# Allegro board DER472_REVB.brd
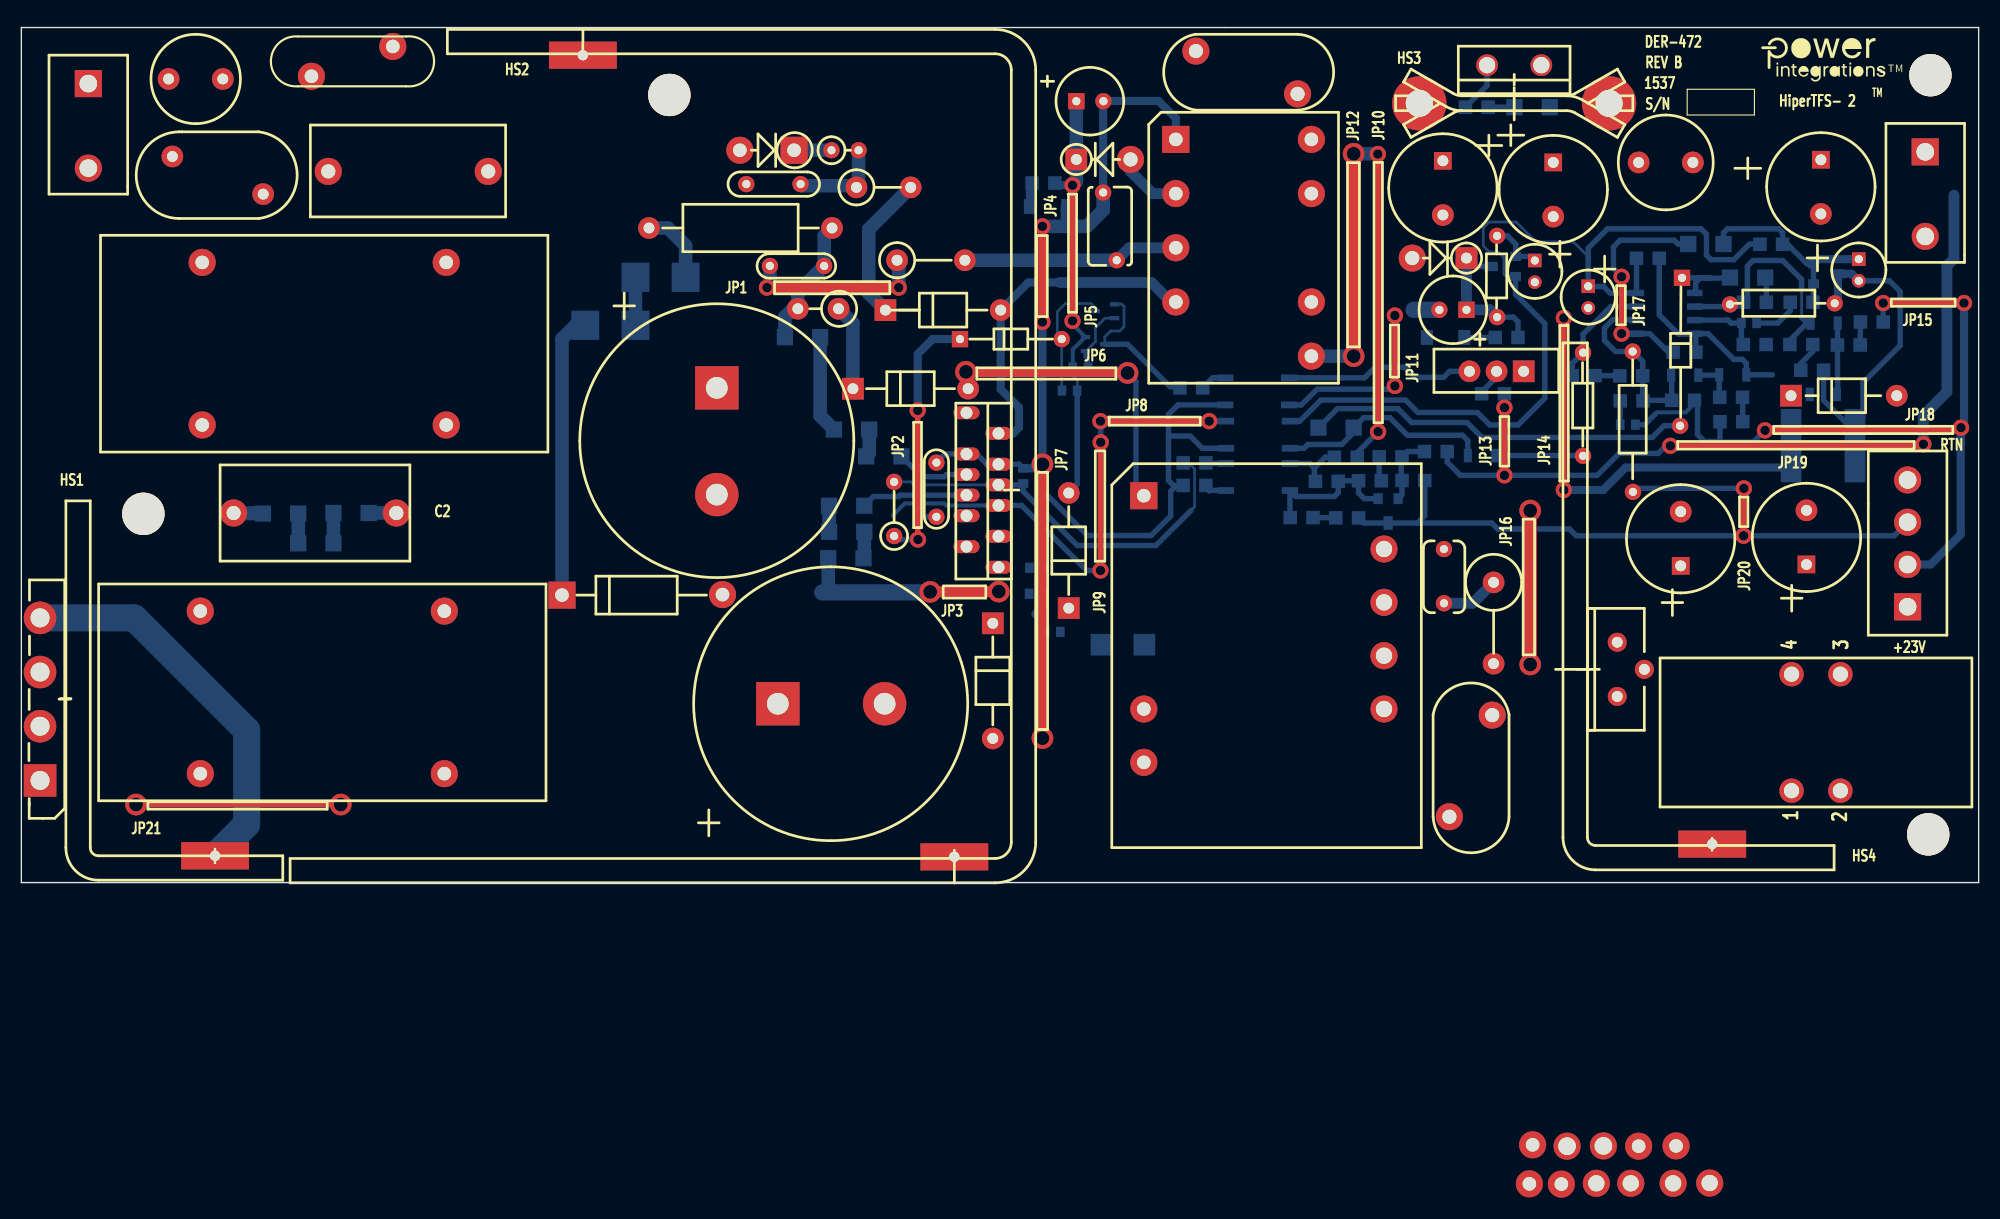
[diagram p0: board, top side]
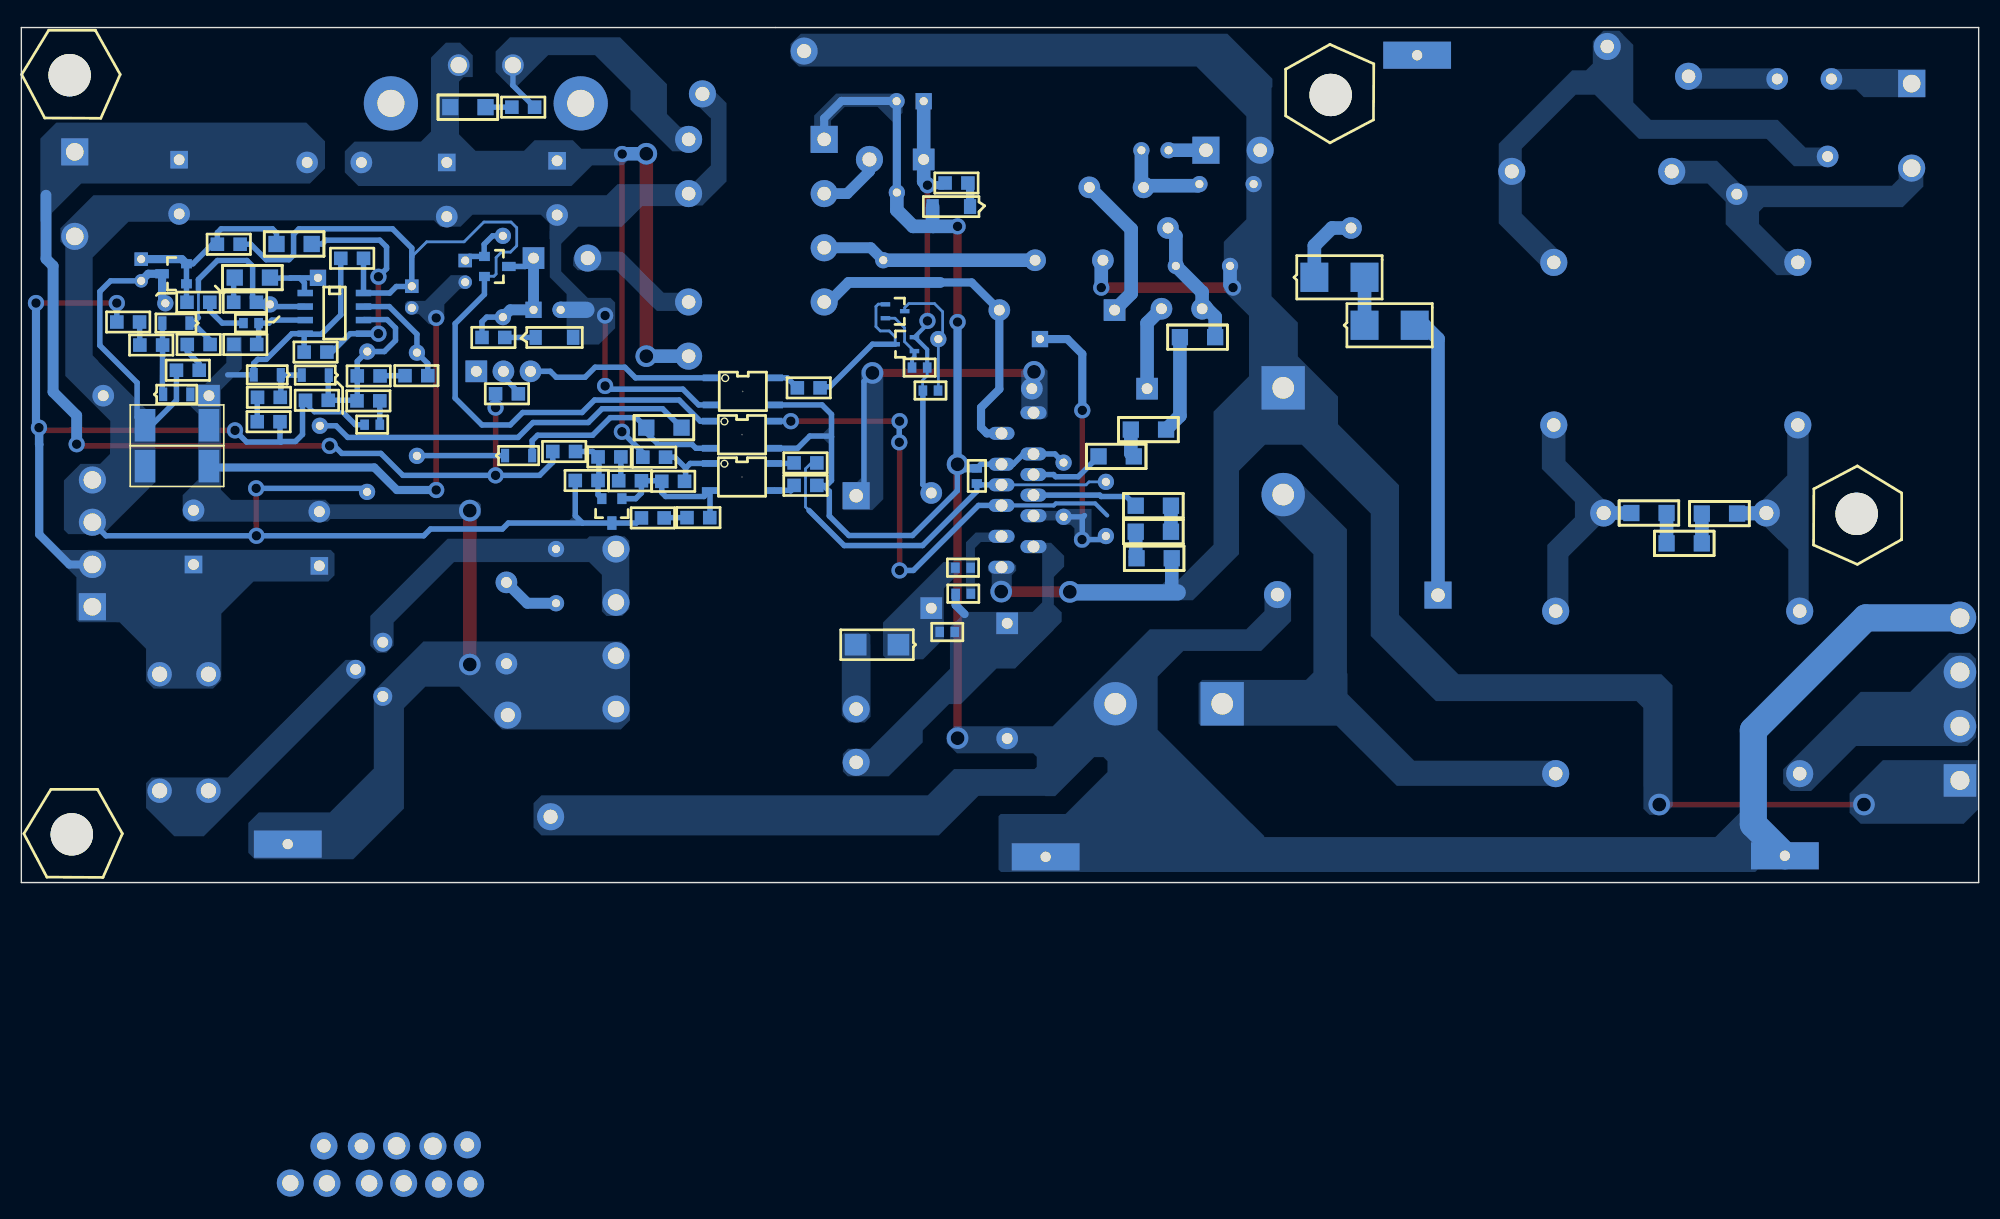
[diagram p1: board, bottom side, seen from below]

Outline 183.36 x 80.16 mm; copper layers: TOP, BOTTOM. Coordinates in mm from the lower left corner of the outline.
Outline path: 0,80.16 183.36,80.16 183.36,0 0,0 0,80.16

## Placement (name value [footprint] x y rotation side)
BR1  GBU8J  [PIDAXBRIDGEGBU8]  1.75 9.58 90 top
C1  220 nF  [PINPXCAPRAD720X340590040]  28.75 66.67 0 top
C2  470 nF  [PI_NP_CAP700X355LS600D040]  35.13 34.65 180 top
C3  680 uF  [PIPOLCAPCLYD948LS394080]  65.18 46.38 270 top
C4  680 uF  [PIPOLCAPCLYD948LS394080]  70.87 16.79 0 top
C5  2.2 nF  [PINPCAPRAD200X100200030]  75.21 57.81 180 top
C6  100 nF  [PISMC0603]  94.41 27.08 0 bottom
C7  100 nF  [PISMC0603]  97.33 23.5 180 bottom
C8  10 uF  [PINPCAPRAD200X100200030]  85.73 34.29 90 top
C9  220pF  [PISMC0603]  93.85 37.41 90 bottom
C10  4.7 nF  [PINPCAPRAD640X260375040]  133.76 6.17 90 top
C11  2.2 nF  [PINPCAPRAD350X100200030]  67.92 65.48 0 top
C12  47 pF  [PINPCAPRAD180X160200030]  133.27 31.27 270 top
C13  150 uF  [PIPOLCAPCYLD400LS200040]  167.23 29.82 90 top
C14  150 uF  [PIPOLCAPCYLD400LS200040]  155.45 29.69 90 top
C15  47 pF  [PISMC0805]  170.13 50.39 0 bottom
C16  680 pF  [PISMC0603]  149.78 42.93 0 bottom
C17  10 nf  [PISMC0805]  145.29 47.52 0 bottom
C18  15 nF  [PISMC0805]  159.11 45.49 0 bottom
C19  10 nf  [PISMC0805]  154.74 49.73 0 bottom
C20  10 uF  [PIPOLCAPCLYD200LS80030]  141.78 58.32 270 top
C21  100 nF  [PISMC0805]  151.31 58.52 0 bottom
C22  10 uF  [PIPOLCAPCLYD200LS80030]  146.79 55.91 270 top
C23  47 nF  [PISMC0805]  163.47 54.41 180 bottom
C24  10 uF  [PIPOLCAPCLYD200LS80030]  172.14 58.45 270 top
C25  15 nF  [PISMC0805]  166.7 48.03 0 bottom
C26  4.7 nF  [PINPCAPRAD640X260375040]  119.56 73.91 180 top
C27  1.0 nF  [PINPCAPRAD290X160250030]  101.35 64.69 270 top
C28  100 uF  [PIPOLCAPCYLD250LS100030]  98.83 73.25 0 top
C29  1 nF  [PISMC0805]  135.28 72.69 0 bottom
C30  100 uF  [PIPOLCAPCYLD250LS100030]  135.38 53.7 180 top
C31  1200 uF  [PIPOLCAPCYLD400LS200040]  133.17 67.67 270 top
C32  1200 uF  [PIPOLCAPCYLD400LS200040]  143.51 67.51 270 top
C33  2.2 uF  [PISMC0805]  121.01 34.21 180 bottom
C34  330 nF  [PISMC0805]  127.2 39.9 0 bottom
C35  330 uF  [PIPOLCAPCYLD400LS200040]  168.58 67.77 270 top
D1  1N4148  [PIDAX375X070030DO35#2]  87.93 50.95 0 top
D2  1N4007  [PIDAX475X125040DO41]  77.9 46.3 0 top
D3  US1D  [PISMDSMA]  101.19 22.3 0 bottom
D4  UF4005  [PIDAX475X125040DO41]  91.01 24.31 270 top
D5  UF4005  [PIDAX475X125040DO41]  98.12 25.73 90 top
D6  1N4007  [PIDV200X110X040DO41#2]  80.95 53.67 0 top
D7  STTH2003CT  [PIDVTO2203VF1]  149.5 19.99 90 top
D8  1N4148  [PIDAX375X070030DO35]  155.42 53.34 270 top
D9  BAV19WS  [PISMSOD323]  138.05 40.03 180 bottom
D10  BAV19WS  [PISMSOD323]  154.56 47.57 0 bottom
D11  BAV19WS  [PISMSOD323]  159.05 47.6 0 bottom
D12  BAV19WS  [PISMSOD323]  170.08 45.77 180 bottom
D13  BAV19WS  [PISMSOD323]  167.61 52.45 0 bottom
D14  1N4002-E3/54  [PIDV200X110X040DO41#3]  165.79 45.64 0 top
D15  UF4003  [PIDV200X110X040DO41]  98.83 67.79 0 top
D16  MBR1045  [PIDVT0220ACREVA]  137.31 76.63 0 top
D17  UF4003  [PIDV200X110X040DO41]  135.38 58.55 180 top
F1  5 A  [PI_TR5_SUBMIN_FUSE]  13.79 75.34 0 top
HS1  HEATSINK, HS POST, PI CUST  [PI_HS_DER472_BRIDGE]  4.17 17.25 270 top
HS2  HEATSINK, HS POST, PI CUST  [PI_HS_DER472_ESIP]  92.74 36.8 90 top
HS3  HEATSINK  [PI_HS_TO220_VERT]  139.85 73.05 0 top
HS4  HEATSINK, HS POST, PI CUST  [PI_HS_DER472_DIODE]  146.71 19.99 270 top
J1  CON3  [PI_HDR_3PIN#2]  6.27 74.9 180 top
J2  CON4  [PI_HDR_4PIN]  176.71 25.86 0 top
J5  CON3  [PI_HDR_3PIN]  178.36 68.5 180 top
L1  7.3 mH  [PIIND4P1650X800LS900X600050]  16.94 42.9 90 top
L2  7.3 mH  [PIIND4P1650X800LS900X600050]  16.76 10.21 90 top
L3  318 uH  [PI_IND_4P_TOROIDAL]  168.12 14.07 90 top
L4  2.2 Uh  [PI_CHOKE_COILCRAFT_RFB0807]  151.51 67.51 0 top
NOREF  -  []  183.36 0 90 top
NOREF#2  -  []  -204.37 -162.2 0 top
NOREF#3  -  []  163.02 79.65 0 top
NOREF#4  -  []  0.03 0 0 top
NOREF#5  -  []  -126.55 36.81 0 top
POST1  Post Hex, 6-32, snap, 0.375L, NYL  [PIMTGHOLED156]  11.43 34.57 270 bottom
POST2  Post Hex, 6-32, snap, 0.375L, NYL  [PIMTGHOLED156]  178.84 75.69 180 bottom
POST3  Post Hex, 6-32, snap, 0.375L, NYL  [PIMTGHOLED156]  178.64 4.52 180 bottom
POST4  Post Hex, 6-32, snap, 0.375L, NYL  [PIMTGHOLED156]  60.71 73.84 90 bottom
Q1  MMST4403-7-F  [PISMSOT323132]  99.7 49.81 90 bottom
Q2  MMST4403-7-F  [PISMSOT323132]  102.41 54.23 270 bottom
Q3  MMBT4401LT1G  [PISMSOT23123_1]  139.98 56.82 270 bottom
R1  680 k  [PISMR1206]  22.63 34.59 0 bottom
R2  680 k  [PISMR1206]  25.93 31.8 0 bottom
R3  680 k  [PISMR1206]  29.24 34.65 0 bottom
R4  82  [PISMR0603]  99.92 48.29 180 bottom
R5  7.5 k  [PISMR0603]  97.49 46.13 0 bottom
R6  10 k  [PISMR0805]  110.67 46.38 180 bottom
R7  100  [PI12WVRESD180LS150D040#2]  58.8 61.37 0 top
R8  931 k  [PISMR1206]  71.53 51.13 0 bottom
R9  931 k  [PISMR1206]  76.12 42.47 0 bottom
R10  976 k  [PISMR1206]  82.45 39.95 180 bottom
R11  931 k  [PISMR1206]  78.89 30.4 180 bottom
R12  931 k  [PISMR1206]  78.97 32.89 180 bottom
R13  976 k  [PISMR1206]  78.97 35.33 180 bottom
R14  2.2  [PI12WVRESD180LS150D040]  72.75 53.8 0 top
R15  1 k  [PISMR0603]  94.44 29.51 0 bottom
R16  107 k  [PI14WVRESD100LS200D030]  81.76 32.49 90 top
R17  0.0  [PISMR0805]  108.84 39.34 0 bottom
R18  0.0  [PISMR0805]  110.97 37.24 180 bottom
R19  22 k  [PI14WVRESD100LS100D030]  75.9 68.66 0 top
R20  6.8  [PI12WVRESD180LS150D040#4]  78.23 65.18 0 top
R21  15  [PI2WVRESD200LS300D040]  137.92 28.14 270 top
R22  10 k  [PISMR0805]  174.42 52.55 180 bottom
R23  3.3 k  [PISMR1206]  121.51 42.65 0 bottom
R24  3.3 k  [PI18WRESD080LS300D030]  146.3 47.62 270 top
R25  33 k  [PISMR0805]  149.76 47.5 0 bottom
R26  15 k  [PISMR0805]  149.78 45.16 0 bottom
R27  232 k  [PISMR0805]  156.74 45.21 180 bottom
R28  10 k  [PISMR0805]  159.13 43.21 0 bottom
R29  10.0 k  [PI14WRESD100LS400D030#2]  150.95 49.78 270 top
R30  10 k  [PISMR1206]  156.16 59.87 0 bottom
R31  10 k  [PI18WVRESD80LS100D030]  138.25 60.63 270 top
R32  4.7 k  [PISMR0805]  162.86 59.84 0 bottom
R33  3.3 k  [PISMR1206]  160.07 56.72 0 bottom
R34  100 k  [PISMR0805]  167.84 54.41 180 bottom
R35  8.66 k  [PISMR0603]  162.56 52.45 180 bottom
R36  15 k  [PI14WRESD100LS400D030]  159.72 54.31 0 top
R37  2.2 k  [PISMR0805]  165.68 50.44 0 bottom
R38  10 k  [PISMR0805]  161.32 50.44 0 bottom
R39  0.1  [PISMR2512]  165.79 39.04 0 bottom
R40  0.1  [PISMR2512]  165.79 42.88 0 bottom
R41  2.2  [PI12WVRESD180LS150D040#3]  82.04 58.34 0 top
R42  1 k  [PISMR0805]  94.69 65.58 0 bottom
R43  4.7  [PISMR1206]  143.18 72.69 180 bottom
R44  1 k  [PISMR0805]  138.07 51.1 0 bottom
R45  100  [PISMR0805]  123.01 39.88 0 bottom
R46  1 k  [PISMR0805]  121.23 37.62 0 bottom
R47  680  [PISMR0805]  123.14 34.19 0 bottom
R48  1 k  [PISMR0805]  125.27 37.67 0 bottom
R49  4.99 k  [PISMR0805]  133.58 40.41 180 bottom
R50  4.7 k  [PISMR0805]  138.94 45.82 180 bottom
R51  4.99 k  [PISMR0805]  129.34 37.69 0 bottom
RT1  2.5  [PI_RAD185X610LS300D031]  27.18 75.59 0 top
RV1  175 VAC  [PI_DISC_575X320_LS335X140D040]  14.15 68.07 0 top
SW1  SPDT SLIDE  [PI_SWITCH_SPDT_SLIDE_PCBM_1]  140.74 47.93 90 top
T1  EER35  [PI_BOBBIN_EER35_14P]  105.16 36.27 0 top
T2  EF25  [PI_BOBBIN_EF25_10P]  108.15 69.67 0 top
U1  TFS-7707H  [PI_IC_ESIP16-12_OVAL_SLOT_RECPT]  91.54 44.04 270 top
U2  LM431BIM3/NOPB  [PISMSOT23123]  167.89 58.01 90 bottom
U3  LM358ADR2G  [PISMSO8]  156.77 55.27 270 bottom
U4  PC357A  [PI_4_SMD]  115.85 41.99 270 bottom
U5  PC357A  [PI_4_SMD]  115.77 46.05 270 bottom
U6  PC357A  [PI_4_SMD]  115.85 38.02 270 bottom
U7  LM431AIM3  [PISMSOT23123]  128.98 35.99 0 bottom
VR1  SMBJ150A  [PISMDO214AA12]  62.23 56.74 180 bottom
VR2  SMBJ150A  [PISMDO214AA12]  57.53 52.25 180 bottom
VR3  P6KE170A  [PIDAX550X140050DO15DO204AC]  50.65 26.95 0 top
VR4  P6KE150A  [PIDV200X140X050DO15DO204AC]  72.39 68.66 180 top
VR5  MMSZ5248B-7-F  [PI_SM_SOD-123_12]  94.49 63.37 0 bottom
VR6  MMSZ5248B-7-F  [PI_SM_SOD-123_12]  135.18 51.1 180 bottom

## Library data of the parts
BR1 = DISCRETE BRIDGE_+~~-
C1 C5-C12 C15-C19 C21 C23 C25-C27 C29 C33 C34 = CAP NP
C2 = CAP NP: tolerance: 20
C3 C4 C13 C14 C31 C32 = CAP POL
C20 C22 C24 = CAP POL: alternate symbols: (pipolcapclyd200ls80030h)
C28 C30 = CAP POL: alternate symbols: (pipolcapclyd250ls100d30h590); tolerance: 20
C35 = CAP POL: alternate symbols: (pipolcapclyd400x530ls200030h)
D1 D8 = DIODE: alternate symbols: (pidax375x070030do35,pidv100x080x030do35)
D2 D6 D14 D15 D17 = DIODE: alternate symbols: (pidax475x125040do41,pidv200x110x040do41wbead,pidax390x125040do41)
D3 D9-D13 = DIODE
D4 D5 = DIODE: alternate symbols: (pidax475x125040do41,pidax390x125040do41)
D7 = D_DUAL_CK_ACA_3: alternate symbols: (pidvto2203vf1)
D16 = DIODE SCHOTTKY
F1 = FUSE
HS1 HS4 = HS-PI_CUSTOM1
HS2 HS3 = HS-PI_CUSTOM2
J1 J5 = CON3
J2 = CON4
L1 L2 = INDUCTOR_4P_revD
L3 = INDUCTOR_4P_SD
L4 = INDUCTOR
POST1-POST4 = POST_CRKT_BRD_6-32_HEX
Q1 Q2 = PNP_BEC
Q3 = NPN_BEC
R1-R6 R8-R11 R17 R18 R22 R23 R25-R28 R30 R32-R35 R37-R40 R42-R51 = R
R7 R14 R20 R41 = R: alternate symbols: (pi12wvresd180ls200d040,pi12wvresd180ls250d040,pi12wresd180ls675d040)
R12 R13 = R: tolerance: 1%
R15 = R: tolerance: 5%
R16 R19 R29 = R: alternate symbols: (pi14wvresd100ls200d030,pi14wresd100ls400d030,pi14wresd100ls500d030)
R21 = R: alternate symbols: (pi2wresd200ls900d040,pi2wvresd200ls300d040,pi2wvresd200ls400d040)
R24 R31 = R: alternate symbols: (pi18wresd080ls300d030)
R36 = R: alternate symbols: (pi14wvresd100ls200d030,pi14wresd100ls400d030,pi14wresd100ls500d030); tolerance: 1%
RT1 = THERMISTOR: alternate symbols: (pi_np_ycap_rad600ls400d040_h)
RV1 = VARISTOR
SW1 = SW SLIDE-SPDT
T1 = BEER35_14P/GENERIC
T2 = BF25_10P/GENERIC
U1 = HiperTFS_II_I_2_ROW: alternate symbols: (pi_ic_esip16-12_oval_slot_recpt)
U2 U7 = TL431/SOT-23_CAR
U3 = LM358
U4-U6 = OPTO_A_B
VR1 VR2 VR5 VR6 = DIODE_ZENER
VR3 VR4 = DIODE_ZENER: alternate symbols: (pidax550x140050do15do204ac)

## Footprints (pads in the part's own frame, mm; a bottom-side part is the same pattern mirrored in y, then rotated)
PI2WVRESD200LS300D040
  round 2.032 hole 1.016: 1(0,0) 2(7.62,0)
PI12WVRESD180LS150D040
  round 2.032 hole 1.016: 1(0,0) 2(3.81,0)
PI12WVRESD180LS150D040#2
  round 2.032 hole 1.016: 1(0,0) 2(17.145,0)
PI12WVRESD180LS150D040#3
  round 2.032 hole 1.016: 1(0,0) 2(6.35,0)
PI12WVRESD180LS150D040#4
  round 2.032 hole 1.016: 1(0,0) 2(5.08,0)
PI14WRESD100LS400D030
  round 1.524 hole 0.762: 1(0.356,-0.102) 2(10.16,0)
PI14WRESD100LS400D030#2
  round 1.524 hole 0.762: 1(0,0) 2(13.157,0.025)
PI14WVRESD100LS100D030
  round 1.524 hole 0.762: 1(0,0) 2(2.54,0)
PI14WVRESD100LS200D030
  round 1.524 hole 0.762: 1(0,0) 2(5.08,0)
PI18WRESD080LS300D030
  round 1.524 hole 0.762: 1(-2.057,0) 2(7.62,0)
PI18WVRESD80LS100D030
  round 1.524 hole 0.762: 1(0,0) 2(7.62,0)
PI_4_SMD
  rect 0.635x1.524 smd: 1(-1.27,-2.997) 2(1.27,-2.997) 3(1.27,2.997) 4(-1.27,2.997)
PI_BOBBIN_EER35_14P
  rect 2.54x2.54 hole 1.27: 1(0,0)
  round 2.54 hole 1.27: 2(36.119,-64.516) 3(39.116,-64.541) 4(36.424,-60.858) 5(0,-20) 6(0,-25.001)
  round 2.54 hole 1.524: 7(45.618,-64.465) 8(49.581,-64.465) 9(53.01,-64.44) 10(22.499,-20) 11(22.499,-15.001) 12(22.499,-10) 13(22.499,-5.001) 14(42.393,-64.465)
PI_BOBBIN_EF25_10P
  rect 2.54x2.54 hole 1.27: 1(0,0)
  round 2.54 hole 1.27: 2(0,-5.08) 3(0,-10.16) 4(0,-15.24) 5(43.358,-94.386) 6(12.7,-20.32) 7(12.7,-15.24) 8(46.863,-94.361) 9(12.7,-5.08) 10(12.7,0)
PI_CHOKE_COILCRAFT_RFB0807
  round 2.032 hole 1.016: 1(0,0) 2(5.08,0)
PI_DISC_575X320_LS335X140D040
  round 2.032 hole 1.016: 1(0,0) 2(8.509,-3.531)
PI_HDR_3PIN
  rect 2.54x2.54 hole 1.651: 1(0,0)
  round 2.54 hole 1.651: 2(30.15,93.193) 3(0,7.925)
PI_HDR_3PIN#2
  rect 2.54x2.54 hole 1.651: 1(0,0)
  round 2.54 hole 1.651: 2(-138.532,99.619) 3(0,7.925)
PI_HDR_4PIN
  rect 2.54x2.54 hole 1.651: 1(0,0)
  round 2.54 hole 1.651: 2(0,3.962) 3(0,7.925) 4(0,11.887)
PI_HS_DER472_BRIDGE
  rect 2.54x6.35 hole 0.965: 1(14.737,13.985)
PI_HS_DER472_DIODE
  rect 2.54x6.35 hole 0.965: 1(16.383,11.694)
PI_HS_DER472_ESIP
  rect 2.54x6.35 hole 0.965: 1(-34.392,5.331) 2(40.762,40.132)
PI_HS_TO220_VERT
  round 5.08 hole 2.54: 1(-8.89,0) 2(8.89,0)
PI_IC_ESIP16-12_OVAL_SLOT_RECPT
  oval 1.219x2.438 hole 1.118: 1(0,-2.997) 3(1.93,0) 5(3.861,-2.997) 6(4.826,0) 7(5.791,-2.997) 8(6.756,0) 9(7.722,-2.997) 10(8.687,0) 11(9.652,-2.997) 13(11.582,0) 14(12.548,-2.997) 16(14.478,0)
PI_IND_4P_TOROIDAL
  round 2.286 hole 1.422: 1(-5.461,2.286) 2(-5.461,-2.286) 3(5.461,-2.286) 4(5.461,2.286)
PI_NP_CAP700X355LS600D040
  round 2.54 hole 1.321: 1(0,0) 2(15.24,0)
PI_RAD185X610LS300D031
  round 2.54 hole 1.27: 1(0,0) 2(7.62,2.794)
PI_SM_SOD-123_12
  rect 1.143x1.397 smd: 1(0,0) 2(3.505,0)
PI_SWITCH_SPDT_SLIDE_PCBM_1
  rect 2.032x2.032 hole 1.016: 1(0,0)
  round 2.032 hole 1.016: 2(0,2.54) 3(0,5.08)
PI_TR5_SUBMIN_FUSE
  round 2.032 hole 1.016: 1(0,0) 2(5.08,0)
PIDAX375X070030DO35
  rect 1.524x1.524 hole 0.762: 1(-3.353,0.152)
  round 1.524 hole 0.762: 2(10.516,-0.025)
PIDAX375X070030DO35#2
  rect 1.524x1.524 hole 0.762: 1(0,0)
  round 1.524 hole 0.762: 2(9.525,0)
PIDAX475X125040DO41
  rect 2.032x2.032 hole 1.016: 1(0,0)
  round 2.032 hole 1.016: 2(10.795,0)
PIDAX550X140050DO15DO204AC
  rect 2.54x2.54 hole 1.27: 1(0,0)
  round 2.54 hole 1.27: 2(15.037,0.051)
PIDAXBRIDGEGBU8
  rect 3.048x3.048 hole 1.778: 1(0,0)
  round 3.048 hole 1.778: 2(5.08,0) 3(10.16,0) 4(15.24,0)
PIDV200X110X040DO41
  rect 2.032x2.032 hole 1.016: 1(0,0)
  round 2.54 hole 1.321: 2(5.08,0)
PIDV200X110X040DO41#2
  rect 2.032x2.032 hole 1.016: 1(0,0)
  round 2.032 hole 1.016: 2(10.795,0)
PIDV200X110X040DO41#3
  rect 2.032x2.032 hole 1.016: 1(0,0)
  round 2.032 hole 1.016: 2(9.906,0)
PIDV200X140X050DO15DO204AC
  rect 2.54x2.54 hole 1.27: 1(0,0)
  round 2.54 hole 1.27: 2(5.08,0)
PIDVT0220ACREVA
  round 2.032 hole 1.524: 1(5.08,0) 2(0,0)
PIDVTO2203VF1
  round 1.778 hole 1.016: 1(-2.54,0) 2(0,-2.54) 3(2.54,0)
PIIND4P1650X800LS900X600050
  round 2.54 hole 1.27: 1(0,0) 2(15.24,0) 3(15.24,-22.86) 4(0,-22.86)
PIMTGHOLED156
  round 3.962 hole 3.962: 1(0,0)
PINPCAPRAD180X160200030
  round 1.524 hole 0.762: 1(0,0) 2(5.08,0)
PINPCAPRAD200X100200030
  round 1.524 hole 0.762: 1(0,0) 2(5.08,0)
PINPCAPRAD290X160250030
  round 1.524 hole 0.762: 1(0,0) 2(6.35,1.27)
PINPCAPRAD350X100200030
  round 1.524 hole 0.762: 1(0,0) 2(5.08,0)
PINPCAPRAD640X260375040
  round 2.54 hole 1.321: 1(0,-0.025) 2(9.525,-4.039)
PINPXCAPRAD720X340590040
  round 2.54 hole 1.321: 1(0,0) 2(14.986,0)
PIPOLCAPCLYD200LS80030
  rect 1.27x1.27 hole 0.762: 1(0,0)
  round 1.27 hole 0.762: 2(2.032,0)
PIPOLCAPCLYD948LS394080
  rect 4.064x4.064 hole 2.032: 1(0,-0.025)
  round 4.064 hole 2.032: 2(10.008,-0.025)
PIPOLCAPCYLD250LS100030
  rect 1.524x1.524 hole 0.762: 1(0,0)
  round 1.524 hole 0.762: 2(2.54,0)
PIPOLCAPCYLD400LS200040
  rect 1.651x1.651 hole 1.016: 1(0,0)
  round 2.032 hole 1.016: 2(5.08,0)
PISMC0603
  rect 0.813x0.965 smd: 1(0,0) 2(1.422,0)
PISMC0805
  rect 1.27x1.27 smd: 1(0,0) 2(2.134,0)
PISMDO214AA12
  rect 2.616x2.743 smd: 1(0,0) 2(4.699,0)
PISMDSMA
  rect 2.032x2.032 smd: 1(0,0) 2(4.013,0)
PISMR0603
  rect 0.813x0.965 smd: 1(0,0) 2(1.422,0)
PISMR0805
  rect 1.27x1.27 smd: 1(0,0) 2(2.134,0)
PISMR1206
  rect 1.524x1.524 smd: 1(0,0) 2(3.302,0)
PISMR2512
  rect 1.93x3.048 smd: 1(0,0) 2(5.994,0)
PISMSO8
  rect 0.61x1.448 smd: 1(0,0) 2(1.27,0) 3(2.54,0) 4(3.81,0) 5(3.81,5.461) 6(2.54,5.461) 7(1.27,5.461) 8(0,5.461)
PISMSOD323
  rect 0.762x1.27 smd: 1(0,0) 2(2.54,0)
PISMSOT23123
  rect 0.864x1.016 smd: 1(-1.88,0) 3(0,0)
  rect 0.864x1.27 smd: 2(-0.94,2.286)
PISMSOT23123_1
  rect 0.864x1.016 smd: 1(-1.88,0) 2(0,0)
  rect 0.864x1.27 smd: 3(-0.94,2.286)
PISMSOT323132
  rect 0.406x0.889 smd: 1(0.018,0) 2(1.321,0) 3(0.66,1.803)

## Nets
+5VS: C35.1 J5.1 L4.2 R49.1 R50.1
GND_SIGNAL: C10.2 C13.2 C14.2 C19.2 C20.2 C21.2 C22.2 D7.1(A1) D11.2 D12.2 D14.1 HS4.1 R21.2 R38.2 R39.1 R40.1 T1.10 T1.11 U3.4(V-)
VCC: C30.1 D17.1 Q3.3(COLLECTOR) R31.2 R44.2
VCCPR: C28.1 D5.2 D15.1 Q1.2(EMITTER) R4.2 R5.2 R42.2
S: BR1.4(-DC) C4.2 C8.2 C9.2 C10.1 C27.1 C28.2 D4.2 HS1.1 HS2.1 R18.2 T2.1 U1.5(G) U1.6(S) U4.3(E) U5.3(E) VR3.2 VR5.2
N6240208: R12.2 R13.2
N6900286: BR1.1(+DC) C3.1 C5.2 C11.1 C26.2 R11.2 R41.1 U1.16(HD) VR4.2
N7091362: C13.1 C14.1 C16.2 J2.1 J2.2 L3.3 L3.4 R22.1 R27.1 R28.1
N7093005: C24.2 C25.2 C26.1 C30.2 C31.2 C32.2 C35.2 D14.2 J2.3 J2.4 J5.3 R29.2 R36.2 R39.2 R40.2 R47.2 R51.2 T2.9 U2.2(A) U5.2(C) U7.2(A) VR6.2
N8059193: C1.2 L1.3 RT1.2 RV1.1
N8059197: F1.1 J1.1
N8059233: C2.1 L1.4 L2.3 R3.2
N8059379: R1.2 R2.1
N8059399: R2.2 R3.1
N8059437: C1.1 J1.3 L1.2 RV1.2
N8059489: C2.2 L1.1 L2.2 R1.1
N8060888: BR1.2(AC1) BR1.3(AC2) L2.1
N8070346: C24.1 R30.2 R32.2 R34.1 U2.1(C) U2.3(VREF)
N8070490: D8.1 R33.1 U3.1(OUT)
N8071028: R35.2 R38.1 U3.3(+IN)
N8073566: C3.2 C4.1 L2.4
N8088388: F1.2 RT1.1
N8130547: R50.2 SW1.2
N8194184: C6.2 C7.2 D4.1 T1.6 U1.14(HS)
N8194788: D2.2 T1.1 U1.1(D)
N8195114: C9.1 R16.2 R17.1 U1.8(EN)
N8203204: C12.1 D7.3(A2) T1.12 T1.13
N8207135: C7.1 D3.1 D5.1 R15.2
N8207503: C6.1 R15.1 U1.13(VDDH)
N8207747: C8.1 D1.1 R16.1 U1.11(BP)
N8210629: C11.2 R19.2 R20.1
N8210678: D6.1 R20.2
N8215309: R9.2 R10.2
N8245190: R11.1 R12.1
N8282330: VR1.2 VR2.1
N8282334: C5.1 R7.2 R8.1 R14.1
N8284357: R7.1 VR1.1
N8290901: C12.2 R21.1
N8293124: D7.2(CATHODE) L3.1 L3.2
N8295742: R8.2 R9.1
N8307586: D2.1 R14.2
N8312021: D1.2 Q2.3(COLLECTOR) R5.1
N8340111: R6.1 U5.4(C)
N8340115: Q1.3(COLLECTOR) Q2.1(BASE) R6.2
N8340130: Q1.1(BASE) Q2.2(EMITTER) R4.1
N8345149: C33.2 R46.2 R48.1 U6.2(C) U7.1(C)
N8345153: R45.1 R46.1 U6.1(A)
N8345627: C31.1 C32.1 D16.1 L4.1 R43.1 R45.2 T2.6
N8345631: C29.1 D16.2 T2.10
N8345647: C34.2 R49.2 R51.1 U7.3(VREF)
N8350160: D3.2 T1.5
N8355512: D8.2 R23.1
N8356324: C21.1 C22.1 Q3.2(EMITTER) R32.1 U3.8(V+) U4.1(A)
N8356492: SW1.3 U5.1(A)
N8357362: C27.2 R41.2 T2.3
N8357377: D6.2 T2.4 U1.3(DSB)
N8358236: C29.2 R43.2
N8360452: VR2.2 VR3.1
N8378806: C34.1 R48.2
N8386529: C23.1 R33.2
N8402614: R10.1 U1.7(R)
N8402673: R13.1 U1.9(L)
N8403112: U1.10(FB) U4.4(C)
N8443298: R42.1 VR5.1
N8443789: D17.2 T2.7
N8454150: R44.1 VR6.1
N8457796: C18.1 D10.2 D11.1
N8460852: C17.1 R24.1 U3.7(OUT)
N8461930: D9.1 R24.2
N8461934: D9.2 R23.2 U4.2(C)
N8468098: C23.2 D13.1 R36.1 R37.1 U3.2(-IN)
N8468110: C15.1 D12.1 D13.2
N8468169: C15.2 R22.2
N8482095: D10.1 R25.2 R26.2 R27.2 R29.1 U3.6(-IN)
N8483580: C19.1 R30.1 U3.5(+IN)
N8501940: C20.1 Q3.1(BASE) R31.1
N8525050: D15.2 T2.2
N8535861: R17.2 U6.4(C)
N8535880: R18.1 U6.3(E)
N8557086: C25.1 R37.2
N80705821: R34.2 R35.1
N80708201: C17.2 R25.1
N82099951: R19.1 VR4.1
N83451930: C33.1 R47.1
N84482650: C16.1 R26.1
N84559551: C18.2 R28.2

Pads without a net: HS2 2; HS3 1 2; J1 2; J5 2; POST1 1; POST2 1; POST3 1; POST4 1; SW1 1; T1 2 3 4 7 8 9 14; T2 5 8

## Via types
v1: diameter 1.524, hole 0.889, TOP to BOTTOM, 30 vias
v2: diameter 2.032, hole 1.295, TOP to BOTTOM, 12 vias

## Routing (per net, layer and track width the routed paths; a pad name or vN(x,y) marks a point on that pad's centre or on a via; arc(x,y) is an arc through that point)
+5VS: length 80
  TOP w0.508: v1(178.18,41.1) 178.03,40.94 v1(154.48,40.94) ; v1(138.94,44.53) v1(138.94,38.18)
  BOTTOM w0.508: v1(138.94,38.18) 147.62,38.18 149.68,40.23 153.34,40.23 154.05,40.94 v1(154.48,40.94) ; v1(138.94,38.18) 134.82,38.18 133.58,39.41 R49.1 ; v1(138.94,38.18) 138.94,38.66 ; v1(138.94,44.53) R50.1
  BOTTOM w1.016: v1(178.18,41.1) 178.18,43.79 180.39,46 180.39,57.81 181.05,58.47 181.05,64.44
GND_SIGNAL: length 73.7
  TOP w0.508: v1(144.5,36.8) v1(144.5,52.93)
  TOP w1.27: v2(141.35,20.45) v2(141.35,34.87)
  BOTTOM w0.508: C19.2 156.87,51.36 U3.4 ; U3.4 158.01,51.46 160.42,49.05 161.22,49.05 161.59,48.68 D11.2 164.03,47.6 ; U3.4 156.72,51.41 155.24,51.41 153.44,53.21 C21.2 ; 165.89,45.75 D14.1
  BOTTOM w0.762: R39.1 165.66,38.91 150.29,38.91 148.18,36.8 v1(144.5,36.8)
  BOTTOM w1.27: D7.1 149.4,17.45 ; 144.48,36.78 v1(144.5,36.8)
VCC: length 14.3
  BOTTOM w0.508: D17.1 136.17,57.76 Q3.3 ; R44.2 140.21,52.58 139.78,53.01 R31.2
  BOTTOM w1.016: D17.1 C30.1 137.57,53.7 R31.2
VCCPR: length 40.2
  TOP w0.508: v1(98.48,65.38) v1(98.48,52.65)
  BOTTOM w0.254: R4.2 98.5,47.52 98.93,47.09 98.93,46.15 R5.2
  BOTTOM w0.381: v1(98.48,52.65) 98.48,52.35 Q1.2 99.65,51.13 98.5,49.98 R4.2
  BOTTOM w0.508: R5.2 98.91,37.31 D5.2
  BOTTOM w0.762: v1(98.48,65.38) 97.03,65.38 R42.2
  BOTTOM w1.27: v1(98.48,65.38) 98.83,65.74 D15.1 C28.1
S: length 163.6
  TOP w0.762: v1(95.66,61.52) v1(95.66,52.55) ; v2(95.66,13.54) v2(95.66,39.22)
  BOTTOM w0.508: 107.47,41.78 107.54,41.86 109.5,41.86 110.64,40.72 U4.3 ; 107.47,41.78 107.47,37.69 107.98,37.19 108.79,37.19 R18.2 108.23,37.24 107.67,36.68 107.67,34.37 105.84,32.54 99.88,32.54 95.68,36.74 95.68,39.19 v2(95.66,39.22) ; 107.47,41.78 107.47,43.89 108.36,44.78 U5.3 ; C8.2 86.54,40.18 89.48,40.18 90.45,39.22 U1.6 93.47,39.22 C9.2
  BOTTOM w0.762: T2.1 108.15,71.65 106.53,73.28 101.4,73.28 C28.2 101.35,73.23 C27.1 ; v1(95.66,52.55) v2(95.66,39.22) 95.28,38.84 C9.2
  BOTTOM w1.27: 97.94,61.52 99.82,61.52 101.35,63.04 C27.1 ; 97.94,61.52 97.99,61.57 VR5.2 ; 97.94,61.52 v1(95.66,61.52)
  BOTTOM w2.54: HS1.1 21.11,5.47 21.11,14.27 10.57,24.82 BR1.4
N6240208: length 5
  BOTTOM w1.016: 75.74,35.38 75.74,32.97 R12.2
  BOTTOM w1.27: R12.2 R13.2
N6900286: length 56.1
  TOP w0.508: v2(10.74,7.32) v2(29.92,7.32)
  TOP w1.016: v1(69.85,55.78) v1(82.19,55.78) ; v2(91.57,27.28) 86.87,27.28 86.84,27.25 v2(85.14,27.25)
  BOTTOM w1.016: 75.69,27.25 75.59,27.36
  BOTTOM w1.27: C5.2 70.13,56.06 v1(69.85,55.78) ; v1(82.19,55.78) 82.19,58.19 R41.1 ; 75.59,27.36 R11.2
  BOTTOM w1.524: v2(85.14,27.25) 85.09,27.2 75.03,27.2
N7091362: length 76.4
  TOP w0.508: v1(181.71,42.65) 181.46,42.39 178.76,42.39 178.73,42.42 177.63,42.42 177.61,42.39 v1(163.35,42.39) ; v1(174.42,54.33) v1(181.99,54.33)
  BOTTOM w0.381: R27.1 156.74,44.91 155.92,44.08 153.23,44.08 153.06,43.92
  BOTTOM w0.508: 159.05,41.3 162.26,41.3 v1(163.35,42.39) ; 159.05,41.3 159,41.35 157.68,41.35 157.02,42.01 157.02,44.93 R27.1 ; 159.05,41.3 159.13,41.38 R28.1 ; R22.1 v1(174.42,54.33) ; 153.06,43.92 152.07,42.93 C16.2
  BOTTOM w0.762: v1(181.71,42.65) 181.69,42.62 181.69,41.07 ; v1(181.71,42.65) 181.99,42.93 v1(181.99,54.33) ; v1(181.71,42.65) 181.71,41.1 181.69,41.07 ; J2.2 178.87,29.82 181.69,32.64 181.69,41.07
N7093005: length 123.1
  TOP w0.508: v1(161.37,36.96) 161.37,33.73 161.34,33.71 v1(161.34,32.51) ; v1(128.68,46.56) v1(128.68,53.16)
  BOTTOM w0.508: U5.2 119.91,44.78 121.39,46.25 128.37,46.25 v1(128.68,46.56) ; 130.78,33.71 U7.2 125.76,33.71 R47.2 ; 130.78,33.71 131.47,34.39 R51.2 ; 130.78,33.71 137.74,33.71 138.3,33.15 145.03,33.15 145.67,32.51 v1(161.34,32.51) 175.44,32.51 J2.3 ; C24.2 175.01,56.41 176.01,55.41 176.01,50.36 172.52,46.86 172.52,43.61 R40.2 171.17,42.88 168.83,45.21 C25.2 ; 150.72,36.37 R29.2 151.31,36.96 v1(161.37,36.96)
  BOTTOM w0.762: C24.2 171.48,57.07 U2.2 170.18,54.61 R36.2
  BOTTOM w1.016: 176.17,38.28 J2.4
  BOTTOM w1.524: C30.2 130.43,53.7
N8059233: length 2.6
  BOTTOM w1.27: C2.1 R3.2
N8059379: length 2.8
  BOTTOM w1.27: R1.2 R2.1
N8059399: length 2.8
  BOTTOM w1.27: R3.1 R2.2
N8059489: length 5.5
  BOTTOM w1.27: C2.2 22.58,34.65 R1.1 19.94,34.59 C2.2
N8070346: length 19.7
  BOTTOM w0.508: R34.1 167.89,54.46 U2.1 U2.3 167.28,58.01 165.46,59.84 R32.2 165,60.93 164.64,61.29 159.84,61.29 159.46,60.91 R30.2
  BOTTOM w0.762: C24.1 168.33,58.45 U2.3
N8070490: length 7
  BOTTOM w0.508: 158.17,56.67 157.28,56.67 156.84,56.24 156.84,55.35 U3.1 ; 158.17,56.67 158.14,56.69 D8.1 ; 158.17,56.67 160.02,56.67 R33.1
N8071028: length 6.6
  BOTTOM w0.508: U3.3 159.89,52.73 160.17,52.45 R35.2 161.14,50.62 R38.1
N8130547: length 2.7
  BOTTOM w0.508: R50.2 136.8,46 138.2,47.4 SW1.2
N8194184: length 2.3
  BOTTOM w0.762: C6.2 95.83,26.01 95,25.17
  BOTTOM w1.524: 90.99,24.32 D4.1
N8194788: length 27.3
  TOP w0.762: v2(103.63,47.78) 88.9,47.78 88.8,47.88 v2(88.49,47.88)
  BOTTOM w0.508: v2(103.63,47.78) 104.42,46.99 104.42,37.01 T1.1
N8195114: length 37.5
  BOTTOM w0.254: 109.58,34.89 109.91,35.22 109.91,38.79 109.35,39.34 R17.1 ; R16.2 83.34,37.57 83.62,37.29 U1.8
  BOTTOM w0.508: 109.58,34.89 106.28,31.6 98.93,31.6 93.85,36.68 C9.1 93.73,37.29 U1.8
N8207747: length 28.5
  TOP w0.508: v1(83.97,44.27) 83.97,32.18 v1(84,32.16)
  BOTTOM w0.508: 83.77,34.42 83.9,34.29 ; 83.9,34.29 C8.1 ; 83.9,34.29 83.97,34.21 83.97,32.18 v1(84,32.16) 82.09,32.16 R16.1
  BOTTOM w0.762: D1.1 85.37,50.95 83.97,49.56 v1(83.97,44.27)
N8210629: length 8.9
  BOTTOM w1.27: R19.2 78.44,65.38 R20.1 78.08,65.33 73.15,65.33 C11.2
N8210678: length 13.8
  BOTTOM w1.27: R20.2 79.39,61.26 79.39,55.23 D6.1
N8215309: length 2.6
  BOTTOM w1.27: R9.2 79.43,40.23 R10.2
N8245190: length 2.5
  BOTTOM w1.27: R12.1 78.97,30.48 R11.1
N8282330: length 4.5
  BOTTOM w1.27: VR1.2 VR2.1
N8282334: length 12.3
  BOTTOM w1.27: R7.2 75.21,60.63 C5.1 72.75,55.35 R14.1 72.29,53.8 71.53,53.04 R8.1
N8284357: length 7.1
  BOTTOM w1.27: VR1.1 62.23,59.72 60.58,61.37 R7.1
N8290901: length 5.5
  BOTTOM w1.016: R21.1 135.97,26.19 C12.2
N8295742: length 9.2
  BOTTOM w1.27: R9.1 74.83,43.76 R8.2
N8307586: length 8.1
  BOTTOM w1.27: D2.1 77.9,52.45 R14.2
N8312021: length 11.9
  BOTTOM w0.254: Q2.3 100.61,53.9 100.23,54.28 97.82,54.28 97.05,53.52 97.05,51.36 D1.2 97.46,46.15 R5.1
N8340111: length 2.5
  BOTTOM w0.508: R6.1 111.61,47.32 U5.4
N8340115: length 14.5
  BOTTOM w0.254: Q2.1 102.43,54.23 103.09,54.23 103.3,54.01 103.3,52.12 102.9,51.71 102.06,51.71 101.5,51.16 Q1.3
  BOTTOM w0.508: Q1.3 103.63,50.47 107.62,46.48 108.43,46.48 R6.2
N8340130: length 6.4
  BOTTOM w0.254: Q1.1 99.74,49.83 100.62,50.71 100.62,52.01 101.52,52.91 Q2.2
  BOTTOM w0.381: R4.1 99.92,49.08 99.7,49.3 Q1.1
N8345149: length 13.6
  BOTTOM w0.508: U7.1 125.81,35.99 125.27,36.53 R48.1 123.42,37.67 R46.2 123.37,36.56 123,36.2 119.41,36.2 U6.2 118.85,34.24 C33.2
N8345153: length 6.1
  BOTTOM w0.508: 121.13,38.86 122.15,39.88 R45.1 ; 121.13,38.86 121.13,37.72 R46.1 ; 121.13,38.86 120.7,39.29 U6.1
N8345627: length 54.5
  TOP w0.508: v1(127.08,68.3) 127.1,68.28 v1(127.1,42.27)
  TOP w1.27: v2(124.82,49.35) v2(124.82,68.33)
  BOTTOM w0.508: R45.2 125.15,40.31 v1(127.1,42.27) ; 142.39,76.61 D16.1
  BOTTOM w1.27: T2.6 v2(124.82,49.35) ; v1(127.08,68.3) 127.05,68.33 v2(124.82,68.33)
N8345631: length 4.8
  BOTTOM w0.508: C29.1 137.31,74.73 D16.2
N8345647: length 6.4
  BOTTOM w0.508: U7.3 129.34,36.35 R51.1 129.26,37.77 129.26,39.83 C34.2 129.84,40.41 R49.2
N8355512: length 36.2
  BOTTOM w0.508: R23.1 123.29,44.42 128.96,44.42 130.25,43.13 135.43,43.13 136.83,41.73 152.79,41.73 153.88,42.82 D8.2
N8356324: length 88.9
  BOTTOM w0.254: Q3.2 139.95,56.85 139.09,56.85 138.89,57.05 138.89,58.6 138.38,59.11 137.54,59.11 136.96,59.69 136.96,61.39 137.49,61.93 140.03,61.93 141.88,60.07 145.39,60.07 146.79,58.67
  BOTTOM w0.508: C21.1 U3.8 148.84,55.27 148.23,55.88 146.81,55.88 C22.1 ; Q3.2 139.98,55.14 142.72,52.4 142.72,45.42 140.21,42.9 137.57,42.9 136.4,44.07 130.84,44.07 129.67,45.24 121.74,45.24 119.76,43.26 U4.1 ; C22.1 146.79,59.49 148.59,61.29 157.35,61.29 157.86,60.78 157.86,58.83 158.29,58.39 160.43,58.39 161.87,59.84 R32.1 ; C22.1 146.74,55.96
N8356492: length 17.9
  BOTTOM w0.508: SW1.3 133.81,47.93 133.25,47.37 130.56,47.37 129.62,48.31 126.82,48.31 125.83,47.32 U5.1
N8357362: length 20.2
  BOTTOM w1.016: C27.2 103.78,59.51 T2.3
  BOTTOM w1.27: C27.2 R41.2
N8357377: length 32.1
  BOTTOM w0.762: 97.28,56.26 94.34,56.26 D6.2 91.74,46.25 93.46,44.54 93.46,42.66 92.91,42.11 U1.3
  BOTTOM w1.016: T2.4 107.7,54.43 105.87,56.26 97.28,56.26
N8358236: length 2.5
  BOTTOM w0.508: C29.2 R43.2
N8360452: length 26.7
  BOTTOM w1.27: VR3.1 50.65,50.98 51.92,52.25 VR2.2
N8378806: length 2.3
  BOTTOM w0.508: R48.2 127.2,37.87 C34.1
N8386529: length 2.4
  BOTTOM w0.508: C23.1 163.47,56.62 R33.2
N8402614: length 7
  BOTTOM w0.508: 88.54,38.25 86.66,38.25 86.46,38.05 84.35,38.05 R10.1
N8402673: length 10
  BOTTOM w0.508: R13.1 79.83,36.2 82.21,36.2 82.34,36.32 88.54,36.32
N8403112: length 48.3
  TOP w0.508: v1(101.09,29.26) 101.09,41.27 v1(101.12,41.27) ; v1(111.28,43.26) v1(101.09,43.26)
  BOTTOM w0.381: U1.10 86.64,35.36 86.45,35.55 82.77,35.55 81.64,34.42
  BOTTOM w0.508: v1(101.09,43.26) 101.12,43.26 v1(101.12,41.27) ; v1(101.09,29.26) 99.79,29.26 93.7,35.36 U1.10 ; U4.4 v1(111.28,43.26)
N8443298: length 2.3
  BOTTOM w0.762: R42.1 94.69,65.53 94.49,65.33 VR5.1
N8454150: length 2.9
  BOTTOM w0.508: VR6.1 R44.1
N8457796: length 4.1
  BOTTOM w0.508: D10.2 159.03,47.57 D11.1 159.05,45.54 C18.1
N8460852: length 10.4
  BOTTOM w0.508: U3.7 148.89,54 146.3,51.41 R24.1 145.29,48.67 C17.1
N8461930: length 8.3
  BOTTOM w0.508: R24.2 146.28,40.03 D9.1
N8461934: length 20.4
  BOTTOM w0.508: U4.2 120.17,40.72 120.52,41.07 123.7,41.07 124.82,42.19 R23.2 125.76,43.59 128.19,43.59 129.84,41.94 135,41.94 135.51,41.43 D9.2
N8468098: length 21.6
  BOTTOM w0.254: 166.78,55.58 166.78,52.96
  BOTTOM w0.508: 166.78,55.58 166.78,56.54 165,58.32 162.23,58.32 161.7,57.78 161.7,54.76 C23.2 161.24,54.31 160.17,54.31 R36.1 159.87,54 U3.2 ; R37.1 165.68,50.85 167.28,52.45 ; 167.28,52.45 D13.1 ; 167.28,52.45 166.78,52.96
N8468110: length 6.7
  BOTTOM w0.508: D13.2 C15.1 170.15,45.85 D12.1
N8468169: length 2.2
  BOTTOM w0.508: R22.2 C15.2
N8482095: length 17.8
  BOTTOM w0.508: U3.6 151.26,52.78 149.1,52.78 148.31,51.99 148.31,50.83 149.35,49.78 R29.1 150.98,49.78 151.89,48.87 R25.2 151.89,45.19 R26.2 151.92,45.21 R27.2 154.61,47.57 D10.1
N8483580: length 21.4
  TOP w0.508: v1(149.91,51.46) v1(149.91,56.79)
  BOTTOM w0.508: C19.1 154.28,49.73 152.55,51.46 U3.5 v1(149.91,51.46) ; v1(149.91,56.79) 149.15,57.56 149.15,59.59 149.78,60.22 154.84,60.22 155.19,59.87 R30.1
N8501940: length 5.2
  BOTTOM w0.508: R31.1 139.22,60.63 140,59.84 140,58.72 Q3.1 141.4,58.7 C20.1
N8525050: length 6.2
  BOTTOM w1.016: D15.2 103.91,66.67 105.99,64.59 T2.2
N8535861: length 1.9
  BOTTOM w0.508: R17.2 111.02,39.29 U6.4
N8535880: length 2.2
  BOTTOM w0.508: R18.1 110.97,37.03 111.28,36.73 111.32,36.77 112.84,36.77 U6.3
N8557086: length 2.9
  BOTTOM w0.508: C25.1 166.73,48.06 166.73,48.69 167.82,49.78 R37.2
N80705821: length 4.4
  BOTTOM w0.508: R35.1 164.54,52.45 165.71,53.62 R34.2
N80708201: length 2.3
  BOTTOM w0.508: R25.1 149.73,47.52 C17.2
N82099951: length 3.5
  BOTTOM w1.27: R19.1 VR4.1
N83451930: length 2.1
  BOTTOM w0.508: R47.1 123.11,34.21 C33.1
N84482650: length 2.3
  BOTTOM w0.508: R26.1 C16.1 149.76,42.95
N84559551: length 2.3
  BOTTOM w0.508: R28.2 161.26,45.47 C18.2

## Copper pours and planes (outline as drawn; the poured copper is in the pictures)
+5VS on BOTTOM: 154.91,69.49 154.91,66.95 156.34,65.53 177.75,65.53 181.33,61.95 181.58,61.95 181.58,69.75 180.09,71.25 156.67,71.25
GND_SIGNAL on BOTTOM: 166.8,43.94 166.8,37.77 168.25,36.32 168.25,34.42 167.67,33.83 154.66,33.83 154.41,34.09 140.69,34.09 140.31,34.47 140.31,35.46 140.56,35.71 141.68,35.71 141.94,35.46 154.46,35.46 154.89,35.89 156.13,35.89 156.15,35.88 163.72,35.88 164.67,36.83 164.67,46.19 164.44,46.41 162.71,48.15 162.71,51.08 162.81,51.18 164.03,51.18 164.16,51.05 164.16,48.72 166.15,46.72 167.7,46.72 167.92,46.51 167.92,45.06
GND_SIGNAL on BOTTOM: 141.66,56.95 143.13,56.95 145.54,54.53 147.19,54.53 147.42,54.31 147.42,53.59 147.12,53.29 146.13,53.29 145.19,52.35 144.14,52.35 143.74,52.76 143.74,54.2 142.29,55.65 141.73,55.65 141.27,56.11 141.2,56.11 141.2,56.49
GND_SIGNAL on BOTTOM: 127.18,22.61 145.69,22.61 150.34,17.96 150.34,10.69 154.46,6.58 161.11,6.58 162.1,5.59 162.1,2.79 161.49,2.18 152.27,2.18 147.52,6.93 147.52,16.36 145.52,18.36 142.34,18.36 138.33,14.35 127.2,14.35 126.34,15.21 126.34,21.77
S on BOTTOM: 107.8,69.19 107.52,69.47 107.52,71.42 106.22,72.72 103.15,72.72 101.73,71.3 101.73,71.25 101.7,71.27 101.5,71.07 101.47,71.09 101.47,71.5 100.81,72.16 100.81,73.51 101.27,73.96 107.04,73.96 109.09,71.91 109.09,69.55 108.74,69.19
S on BOTTOM: 107.34,42.93 107.44,42.93 108.23,42.14 108.23,41.63 107.42,40.82 107.24,41 107.24,42.82
S on BOTTOM: 67.21,21.72 64.41,24.51 64.41,27.58 65,28.17 66.32,28.17 66.9,27.58 66.9,25.45 68.61,23.75 77.65,23.75 86.74,14.66 95.96,14.66 96.67,13.94 96.67,13.08 95.69,12.1 95.68,12.12 88.57,12.12 88.24,11.79 88.24,10.85 88.44,10.64 95.99,10.64 98.45,8.18 134.65,8.18 135.38,7.44 135.38,5.16 134.65,4.42 97.41,4.42 93.7,8.13 87.45,8.13 87.43,8.1 86.51,8.1 82.85,11.76 81.99,11.76 81.61,11.38 81.61,10.36 85.55,6.43 91.62,6.43 91.82,6.22 91.82,1.22 91.59,0.99 20.93,0.99 20.55,1.37 20.55,6.3 21.59,7.34 24.66,4.27 66.93,4.27 66.93,4.37 68.1,5.54 68.12,5.54 76.91,14.33 76.91,19.3 74.5,21.72
N6900286 on BOTTOM: 69.57,57.63 69.57,57.53 68.25,56.21 68.35,56.11 69.72,56.11 69.72,57.48
N6900286 on BOTTOM: 90.35,29.9 92.56,29.9 92.81,29.64 92.81,29.26 92.46,28.91 92.46,27 91.95,26.49 91.14,26.49 90.58,27.05 90.58,28.83 90.2,29.21 90.17,29.21 90.17,29.72
N6900286 on BOTTOM: 0.08,11.48 0.08,6.83 1.4,5.51 11.05,5.51 12.09,6.55 12.09,8.36 8.97,11.48
N6900286 on BOTTOM: 68.35,47.47 71.68,44.15 71.68,31.67 75.03,28.32 76.12,28.32 76.53,27.91 76.53,26.82 76.17,26.47 73.61,26.47 69.29,30.78 69.29,38.61 66.85,41.05 63.4,41.05 56.95,34.59 56.95,23.11 50.85,17.02 32.05,17.02 31.42,16.38 31.42,9.02 31.41,9 31.41,6.92 30.84,6.35 29.46,6.35 28.68,7.14 28.68,18.49 29.72,19.53 48.74,19.53 54.31,25.1 54.31,37.26 60.02,42.98 60.02,45.57 63.78,49.33 63.78,52.5 66.24,54.97 66.24,74.5 66.17,74.57 66.17,75.36 70.38,79.58 110.34,79.58 111.3,78.61 111.3,77.29 110.52,76.5 73.28,76.5 68.61,71.83 68.61,62.18 70.71,60.07 70.71,55.5 68.35,53.14
N7091362 on BOTTOM: 178.21,28.63 178.21,24.64 177.98,24.41 174.47,24.41 174.46,24.4 174.16,24.4 171.68,21.92 171.68,18.9 170.97,18.19 165.4,18.19 164.63,18.96 164.63,25.21 161.62,28.22 154.61,28.22 154.03,28.8 154.03,30.84 154.38,31.19 177.14,31.19 177.15,31.18 179.92,31.18 180.01,31.09 180.01,30.43
N7093005 on BOTTOM: 131.52,34.75 131.6,34.75 131.72,34.62 131.72,34.26 132.18,33.81 132.08,33.71 131.04,33.71 131.04,34.26
N7093005 on BOTTOM: 178.97,32.66 175.69,32.66 170.81,37.54 170.81,44.4 171.7,44.4 176.15,48.84 176.15,48.9 176.68,49.43 176.68,58.6 173.33,61.95 168.15,61.95 168.02,62.08 144.7,62.08 144.12,61.49 142.21,61.49 141.1,62.61 134.7,62.61 133.88,61.8 133.88,60.35 133.48,59.94 133.48,59.56 133.12,59.56 131.19,61.49 127.1,61.49 125.17,63.42 120.68,63.42 119.94,64.16 119.94,65.18 120.24,65.48 127.51,65.48 128.55,64.44 176.61,64.44 179.7,61.34 179.7,60.1 179.25,59.64 179.25,47.5 175.03,43.28 175.03,40.72 175.06,40.69 175.06,40.18 175.98,39.26 177.81,39.26 179.37,37.69 179.37,33.07
N7093005 on BOTTOM: 128.17,54.81 130.3,54.81 132.79,57.3 132.79,60.22 133.86,61.29 133.86,56.74 132.28,55.17 132.28,50.44 129.26,50.44 127.74,51.97 127.74,54.38
N7093005 on BOTTOM: 119.13,74.9 119.94,74.9 120.62,74.22 120.62,73.48 118.85,71.7 118.82,71.7 118.77,71.65 118.77,67.23 120.52,65.48 121.01,65.48 121.01,63.55 120.93,63.47 119.56,63.47 117.3,65.74 117.3,73.08
N8059193 on BOTTOM: 13.72,68.91 16.23,68.91 18.82,71.5 30.71,71.5 32.36,73.15 32.36,78.54 33.3,79.48 33.3,79.53 33.32,79.53 33.66,79.86 35.15,79.86 36.14,78.87 36.14,76.78 36.78,76.15 38.07,76.15 44.96,69.27 44.96,61.8 40.28,57.12 39.47,57.12 38.76,57.84 38.76,58.67 42.8,62.71 42.8,68.81 37.74,73.86 35.97,73.86 31.83,69.72 19.86,69.72 17.3,67.16 13.77,67.16 13.36,67.56 13.36,68.55
N8059197 on BOTTOM: 5.03,76.28 14.1,76.28 14.55,75.82 14.55,74.88 14.02,74.35 11.48,74.35 10.77,73.63 4.98,73.63 4.98,76.23
N8059233 on BOTTOM: 34.82,35.79 34.98,35.79 38.71,39.52 38.71,43.36 39.22,43.87 40.39,43.87 40.92,43.33 40.92,38.79 37.82,35.69 37.82,34.24 40.41,31.65 40.41,24.92 40.06,24.56 38.94,24.56 38.43,25.07 38.43,30.58 35.51,33.5 34.72,33.5 34.14,34.09 34.14,35.1
N8059437 on BOTTOM: 5.77,67.97 6.91,67.97 7.49,67.39 7.49,65.96 8.13,65.33 22.17,65.33 24.51,67.67 29.06,67.67 29.64,67.08 29.64,66.12 29.06,65.53 25.4,65.53 23.7,63.83 23.7,61.72 18.92,56.95 16.59,56.95 15.93,57.61 15.93,58.67 16.46,59.21 18.03,59.21 20.57,61.75 20.57,62.89 20.14,63.32 7.11,63.32 5.18,65.25 5.18,67.39
N8059489 on BOTTOM: 16.23,43.81 17.6,43.81 17.93,43.48 17.93,38.18 20.6,35.51 20.6,33.96 18.72,32.08 18.67,32.08 17.83,31.24 17.83,25.22 16.99,24.38 16.43,24.38 15.93,24.89 15.93,43.41 15.88,43.46
N8060888 on BOTTOM: 0.25,20.98 0.25,13.61 1.07,12.8 11.48,12.8 15.7,8.59 17.63,8.59 18.31,9.27 18.31,10.62 11.05,17.88 6.4,17.88 2.74,21.54 0.81,21.54
N8073566 on BOTTOM: 64.39,38.33 59.18,33.12 59.18,19.63 59.13,19.58 59.13,17.68 52.88,11.43 39.29,11.43 38.94,11.07 38.94,9.63 39.5,9.07 54.51,9.07 60.15,14.71 72.87,14.71 73.08,14.91 73.08,18.67 72.75,19 63.02,19 62.32,19.7 62.32,30.77 66.93,35.38 66.93,37.19 65.79,38.33
N8088388 on BOTTOM: 18.54,76.33 27.51,76.33 27.81,76.02 27.81,75.06 27.18,74.42 18.47,74.42 18.14,74.75 18.14,75.92
N8194184 on BOTTOM: 86.64,28.65 86.64,26.06 85.88,25.3 85.9,25.27 85.9,24.46 86.64,23.72 86.64,23.7 90.27,20.07 92.01,20.07 94.06,18.02 95.35,16.73 96.45,16.73 98.92,14.26 98.92,13.14 102.11,9.96 105.94,9.96 106.4,10.41 106.4,12.06 105.92,12.55 103.86,12.55 96.37,20.04 96.37,23.95 94.95,25.37 88.62,25.37 87.73,26.26 87.73,30.81 87.86,30.94 89.36,30.94 89.43,31.01 89.43,31.78 89.36,31.85 86.87,31.85 86.87,31.83 85.67,30.63 85.67,29.62
N8194788 on BOTTOM: 87.86,48.62 89,48.62 89.69,47.93 89.69,43.74 89.43,43.48 87.43,43.48 87.22,43.69 87.22,47.98
N8194788 on BOTTOM: 106.36,34.92 103.63,34.92 102.62,35.94 102.62,48.16 103.1,48.64 104.09,48.64 104.7,48.03 104.7,37.92 105.07,37.55 106.36,37.55
N8203204 on BOTTOM: 126.42,25.65 126.42,32.03 126.85,32.46 130.15,32.46 130.38,32.23 143.43,32.23 150.67,24.99 150.67,22.2 150.01,21.54 149.17,21.54 148.49,22.23 148.49,24.38 142.82,30.05 130.17,30.05 128.98,28.85 128.98,25.43 128.55,24.99 127.08,24.99
N8207135 on BOTTOM: 102.64,24.38 102.64,21.29 102.29,20.93 98.88,20.93 96.94,22.87 96.94,27.57 95.45,29.06 95.45,30 95.5,30.05 96.98,30.05
N8207503 on BOTTOM: 90.5,32.82 93.95,32.82 94.87,31.9 94.87,26.67 94.82,26.62 94.06,26.62 94.03,26.64 94.03,31.37 93.47,31.93 90.5,31.93 90.35,32.08 90.35,32.66
N8207747 on BOTTOM: 88.75,34.85 89.13,34.47 89.13,34.01 89.07,33.95 86.42,33.95 86.02,33.54 85.05,33.54 84.71,33.2 84.71,31.78 84.33,31.39 83.67,31.39 83.11,31.95 83.11,35.03 85.93,35.03 86.11,34.85
N8293124 on BOTTOM: 151.76,20.88 152.98,20.88 164.01,9.86 171.15,9.86 171.68,9.32 171.68,6.99 169.04,4.34 166.27,4.34 151.1,19.51 151.1,20.22
N8345627 on BOTTOM: 130.9,68.8 131.7,69.6 135.28,69.6 136.27,68.61 140.82,68.61 142.37,70.15 142.37,75.08 141.94,75.51 141.07,75.51 141.07,77.55 142.27,78.74 143.59,78.74 144.98,77.34 144.98,70.41 145.92,69.47 152.15,69.47 153.06,68.55 153.06,66.57 151.79,65.3 131.83,65.3 129.9,67.23 127,67.23 126.47,67.77 126.47,68.61 126.67,68.81 126.68,68.8
N8345631 on BOTTOM: 121.67,70.84 120.45,70.84 119.76,70.15 119.76,69.29 120.5,68.55 122.38,68.55 126.3,72.48 126.3,74.26 129.64,77.6 129.64,77.57 134.01,77.57 137.01,74.57 137.52,74.57 138.94,76 138.94,77.9 137.59,79.25 127.28,79.25 122.89,74.85 122.89,72.06
N8350160 on BOTTOM: 106.5,15.67 105.84,15.01 104.34,15.01 103.81,15.54 103.81,22.3 103.82,22.31 103.82,23.23 104.04,23.44 106.27,23.44 106.5,23.22
N8443789 on BOTTOM: 120.47,55.3 123.19,55.3 127.05,59.16 131.11,59.16 131.67,58.6 131.67,57.84 131.24,57.4 127.64,57.4 123.83,53.59 120.5,53.59 120.12,53.98 120.12,54.94

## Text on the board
Ref Des/Silkscreen Top: TM | JP21 | JP1 | JP3 | JP6 | JP8 | 1537 | DER-472 | REV B | S/N | JP19 | HiperTFS- 2 | +23V | JP15 | JP18 | RTN | JP2 | JP4 | JP7 | JP5 | JP9 | JP12 | JP10 | JP11 | JP13 | JP16 | JP14 | JP17 | JP20
PAGE_OUTLINE: PLEASE DELETE THESE PINS | 13   MATERIAL FR4 COPPER 2oz THICKNESS 0.062" | SLOT OUTLINE
User.5: FIGURE | SIZE | 30.0 | 35.0 | 38.0 | 40.0 | 44.0 | 50.0 | 51.0 | 52.0 | 56.0 | 60.0 | 65.0 | 70.0 | 80.0 | 100.0 | 156.0 | DRILL CHART: TOP to BOTTOM | ALL UNITS ARE IN MILS | PLATED | QTY | 36 | 30 | 4 | 44 | 12 | 10 | 2
